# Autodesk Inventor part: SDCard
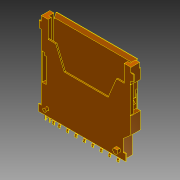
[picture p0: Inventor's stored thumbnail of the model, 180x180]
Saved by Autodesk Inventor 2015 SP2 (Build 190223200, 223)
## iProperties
Created: 2015-08
Part Number: SDCard
Material: Allgemein
Document SubType Name: Modeling
Designer: rYan
Density: 1 g/cm^3
Appearance: Vorgabe
Author: workeradm
Title: c-2041021-3-b-3d.igs
Organization: Unknown
Description: PTC IGES file: c-2041021-3-b-3d.igs
Sending System: Creo Parametric by Parametric Technology Corporation
Preprocessor: 2013050
Minimum Resolution: 0.003864
Sending System Product ID: C-2041021-3
Receiving System Product ID: C-2041021-3
Sent Units: Millimeter
Translation Standard: USPRO/IPO100 IGES 5.2
Author: rYan
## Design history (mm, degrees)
node "c-2041021-3-b-3d1"
feature "Zusammengesetzt1"
node "Fläche1"
